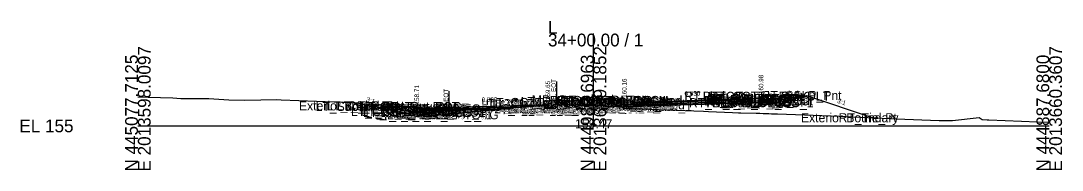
# Model space of a CAD drawing. Extents: x -26 to 4203, y -10 to 9526.
# Drawn here: x 1974.3 to 2202.8, y 3990.3 to 4023 of the extents above; entities that cross this region are included whole.
import ezdxf

# ---------------------------------------------------------------- set-up
doc = ezdxf.new("R2010")
doc.units = 0
for name, color, linetype in [('Default', 7, 'Continuous'), ('Exist CMT Pavement', 7, 'Continuous'), ('Exist Cross Section Cell', 7, 'Continuous'), ('Exist XS Center Line Elevation Label', 7, 'Continuous'), ('Exist XS Ground Line', 7, 'Continuous'), ('Prop CMT Conc Surface', 7, 'Continuous'), ('Prop CMT Concrete Structures', 7, 'Continuous'), ('Prop CMT Pvmt Course 1', 7, 'Continuous'), ('Prop CMT Pvmt Course 1 CG', 7, 'Continuous'), ('Prop CMT Pvmt Course 2', 7, 'Continuous'), ('Prop CMT Pvmt Course 2 Wedge', 7, 'Continuous'), ('Prop CMT Pvmt Course 3', 7, 'Continuous'), ('Prop CMT Pvmt Course 3 Wedge', 7, 'Continuous'), ('Prop CMT Pvmt Surface', 7, 'Continuous'), ('Prop CMT Slope Grass', 7, 'Continuous'), ('Prop CMT Subgrade Earthwork', 7, 'Continuous'), ('Prop XS Hydro Elevations', 7, 'Continuous'), ('Prop XS Label Text', 7, 'Continuous'), ('Prop XS SE Text', 7, 'Continuous'), ('Prop XS Side Slope Text', 7, 'Continuous'), ('Scratch_Level_0', 7, 'Continuous')]:
    doc.layers.add(name, color=color, linetype=linetype)

msp = doc.modelspace()

# ---------------------------------------------------------------- linework, layer by layer
at = {"layer": 'Exist CMT Pavement'}
msp.add_lwpolyline([(2067.12, 4002.45), (2067.13, 4002.45), (2067.16, 4002.46), (2068.21, 4002.58), (2068.52, 4002.61), (2069.01, 4002.66), (2071.22, 4002.88), (2072.32, 4002.99), (2073.85, 4003.16), (2076.18, 4003.37), (2076.47, 4003.39), (2076.62, 4003.4), (2077.08, 4003.45), (2079.21, 4003.65), (2079.59, 4003.68), (2080.15, 4003.74), (2081.71, 4003.88), (2084.01, 4004.11), (2084.33, 4004.14), (2084.99, 4004.19), (2086.46, 4004.32), (2086.96, 4004.36), (2087.93, 4004.44), (2089.59, 4004.57), (2091.11, 4004.67), (2091.25, 4004.68)], dxfattribs=at)
at = {"layer": 'Exist Cross Section Cell'}
for p, q in [((2100, 4000), (2100, 4020.22)), ((2000, 4000), (2100, 4000)), ((2100, 4000), (2200, 4000))]:
    msp.add_line(p, q, dxfattribs=at)
at = {"layer": 'Exist XS Ground Line'}
msp.add_lwpolyline([(2000, 4006.35), (2002.22, 4006.27), (2007.64, 4006.14), (2009.42, 4006.04), (2015.57, 4005.97), (2019.95, 4005.74), (2023.49, 4005.64), (2030.47, 4005.75), (2031.42, 4005.73), (2046.98, 4005.12), (2048.18, 4005.07), (2049.4, 4004.79), (2059.55, 4002.61), (2063.84, 4002.53), (2067.11, 4002.45), (2068.21, 4002.58), (2068.52, 4002.61), (2069.01, 4002.66), (2071.22, 4002.88), (2072.32, 4002.99), (2073.85, 4003.16), (2076.62, 4003.4), (2077.08, 4003.45), (2079.21, 4003.65), (2079.59, 4003.68), (2080.15, 4003.74), (2081.71, 4003.88), (2084.01, 4004.11), (2084.33, 4004.14), (2084.99, 4004.19), (2086.46, 4004.32), (2086.96, 4004.36), (2087.93, 4004.44), (2089.59, 4004.57), (2091.11, 4004.67), (2091.84, 4004.71), (2094.89, 4004.62), (2098.89, 4004.5), (2100, 4004.47), (2106.09, 4004.29), (2106.59, 4003.89), (2122.02, 4003.29), (2124.09, 4003.23), (2125.2, 4003.18), (2130.46, 4002.97), (2131.84, 4002.9), (2132.29, 4002.89), (2135.7, 4002.79), (2136.49, 4002.77), (2137.21, 4002.74), (2137.88, 4002.72), (2138.49, 4002.7), (2139.04, 4002.68), (2139.53, 4002.67), (2139.96, 4002.65), (2140.34, 4002.64), (2146.26, 4002.39), (2153.93, 4002.1), (2156.78, 4002), (2158.63, 4001.91), (2166.38, 4001.58), (2175.84, 4001.19), (2178.74, 4001.15), (2184.63, 4001.83), (2185.31, 4001.38), (2186.37, 4001.32), (2186.71, 4001.3), (2193.89, 4001.02), (2197.32, 4000.91), (2200, 4000.85)], dxfattribs=at)
at = {"layer": 'Prop CMT Conc Surface'}
for points in [[(2136.75, 4005.98), (2136.75, 4006.48), (2137.25, 4006.48)], [(2141.25, 4006.57), (2146.25, 4006.67)], [(2058.75, 4004.25), (2053.75, 4004.35)], [(2061.2, 4003.71), (2061.2, 4004.21), (2060.7, 4004.21)], [(2089.22, 4004.63), (2089.97, 4004.65), (2089.97, 4004.82), (2090.73, 4005.07)], [(2108.75, 4005.22), (2106.75, 4005.16), (2106.75, 4005.32), (2106, 4005.57)], [(2134.75, 4006), (2136.75, 4005.98)], [(2063.2, 4003.85), (2061.2, 4003.71)]]:
    msp.add_lwpolyline(points, dxfattribs=at)
at = {"layer": 'Prop CMT Concrete Structures'}
for points in [[(2134.75, 4006), (2136.75, 4005.98), (2136.75, 4006.48), (2137.25, 4006.48)], [(2137.25, 4006.48), (2137.25, 4005.49), (2134.75, 4005.41)], [(2146.25, 4006.67), (2141.25, 4006.57)], [(2141.25, 4006.57), (2141.25, 4006.23)], [(2141.25, 4006.23), (2146.25, 4006.33)], [(2146.25, 4006.33), (2146.25, 4006.67)], [(2053.75, 4004.02), (2053.75, 4004.35)], [(2053.75, 4004.35), (2058.75, 4004.25)], [(2058.75, 4003.92), (2053.75, 4004.02)], [(2058.75, 4004.25), (2058.75, 4003.92)], [(2063.2, 4003.85), (2061.2, 4003.71), (2061.2, 4004.21), (2060.7, 4004.21)], [(2060.7, 4004.21), (2060.7, 4003.19), (2063.2, 4003.27)], [(2089.22, 4004.63), (2089.97, 4004.65), (2089.97, 4004.82), (2090.73, 4005.07)], [(2089.22, 4004.05), (2089.22, 4004.63)], [(2090.73, 4004.09), (2089.22, 4004.05)], [(2090.73, 4005.07), (2090.73, 4004.09)], [(2108.75, 4005.22), (2106.75, 4005.16), (2106.75, 4005.32), (2106, 4005.57)], [(2106, 4005.57), (2106, 4004.55)], [(2106, 4004.55), (2108.75, 4004.63)], [(2108.75, 4004.63), (2108.75, 4005.22)], [(2134.75, 4005.41), (2134.75, 4006)], [(2063.2, 4003.27), (2063.2, 4003.85)]]:
    msp.add_lwpolyline(points, dxfattribs=at)
at = {"layer": 'Prop CMT Pvmt Course 1'}
for points in [[(2089.22, 4004.63), (2063.2, 4003.85)], [(2063.2, 4003.6), (2067.12, 4003.72), (2089.22, 4004.38)], [(2089.22, 4004.38), (2089.22, 4004.63)], [(2089.22, 4004.38), (2089.22, 4004.38)], [(2108.75, 4005.22), (2134.75, 4006)], [(2134.75, 4005.75), (2108.75, 4004.97)], [(2108.75, 4004.97), (2108.75, 4005.22)], [(2108.75, 4004.97), (2108.75, 4004.97), (2108.75, 4004.97)], [(2134.75, 4006), (2134.75, 4005.75)], [(2063.2, 4003.85), (2063.2, 4003.6)]]:
    msp.add_lwpolyline(points, dxfattribs=at)
at = {"layer": 'Prop CMT Pvmt Course 1 CG'}
for points in [[(2089.22, 4004.05), (2091.23, 4004.11), (2091.55, 4003.79)], [(2089.22, 4003.72), (2089.22, 4004.05)], [(2108.75, 4004.63), (2105.5, 4004.54), (2105.16, 4004.19)], [(2105.16, 4004.19), (2108.75, 4004.3)], [(2108.75, 4004.3), (2108.75, 4004.63)], [(2134.75, 4005.41), (2137.75, 4005.5), (2138.07, 4005.18)], [(2134.75, 4005.08), (2134.75, 4005.41)], [(2138.07, 4005.18), (2134.75, 4005.08)], [(2063.2, 4003.27), (2060.2, 4003.18), (2059.86, 4002.83)], [(2059.86, 4002.83), (2063.2, 4002.93)], [(2063.2, 4002.93), (2063.2, 4003.27)], [(2091.55, 4003.79), (2089.22, 4003.72)]]:
    msp.add_lwpolyline(points, dxfattribs=at)
at = {"layer": 'Prop CMT Pvmt Course 2'}
msp.add_lwpolyline([(2089.22, 4004.38), (2089.22, 4004.05), (2089.22, 4004.05)], close=True, dxfattribs=at)
for points in [[(2089.22, 4004.38), (2089.22, 4004.38)], [(2108.75, 4004.97), (2134.75, 4005.75)], [(2134.75, 4005.41), (2108.75, 4004.63)], [(2108.75, 4004.63), (2108.75, 4004.97)], [(2134.75, 4005.75), (2134.75, 4005.41)], [(2067.12, 4003.72), (2063.2, 4003.6)], [(2063.2, 4003.6), (2063.2, 4003.27)], [(2063.2, 4003.27), (2067.12, 4003.39)], [(2067.12, 4003.39), (2067.12, 4003.72)]]:
    msp.add_lwpolyline(points, dxfattribs=at)
at = {"layer": 'Prop CMT Pvmt Course 2 Wedge'}
for points in [[(2067.12, 4003.72), (2067.13, 4003.72), (2067.16, 4003.72), (2068.21, 4003.75), (2068.52, 4003.76), (2069.01, 4003.77), (2071.22, 4003.84), (2072.32, 4003.87), (2073.85, 4003.92), (2076.18, 4003.99), (2076.47, 4004), (2076.62, 4004), (2077.08, 4004.02), (2079.21, 4004.08), (2079.59, 4004.09), (2080.15, 4004.11), (2081.71, 4004.16), (2084.01, 4004.22), (2084.33, 4004.23), (2084.99, 4004.25), (2086.03, 4004.29)], [(2086.03, 4004.29), (2084.99, 4004.19), (2084.33, 4004.14), (2084.01, 4004.11), (2081.71, 4003.88), (2080.77, 4003.79), (2080.15, 4003.78), (2079.59, 4003.76), (2079.21, 4003.75), (2077.08, 4003.68), (2076.62, 4003.67), (2076.47, 4003.67), (2076.18, 4003.66), (2073.85, 4003.59), (2072.32, 4003.54), (2071.22, 4003.51), (2069.01, 4003.44), (2068.52, 4003.43), (2068.21, 4003.42), (2067.16, 4003.39), (2067.13, 4003.39), (2067.12, 4003.38)], [(2067.12, 4003.38), (2067.12, 4003.72)]]:
    msp.add_lwpolyline(points, dxfattribs=at)
at = {"layer": 'Prop CMT Pvmt Course 3'}
for points in [[(2089.22, 4004.05), (2089.22, 4004.05), (2089.22, 4003.72), (2089.22, 4003.72)], [(2089.22, 4003.72), (2089.22, 4004.05)], [(2108.75, 4004.63), (2134.75, 4005.41)], [(2134.75, 4005.08), (2108.75, 4004.3)], [(2108.75, 4004.3), (2108.75, 4004.63)], [(2134.75, 4005.41), (2134.75, 4005.08)], [(2067.12, 4003.39), (2063.2, 4003.27)], [(2063.2, 4003.27), (2063.2, 4002.93)], [(2063.2, 4002.93), (2067.12, 4003.05)], [(2067.12, 4003.05), (2067.12, 4003.39)]]:
    msp.add_lwpolyline(points, dxfattribs=at)
at = {"layer": 'Prop CMT Pvmt Course 3 Wedge'}
for points in [[(2067.12, 4003.39), (2067.13, 4003.39), (2067.16, 4003.39), (2068.21, 4003.42), (2068.52, 4003.43), (2069.01, 4003.44), (2071.22, 4003.51), (2072.32, 4003.54), (2073.85, 4003.59), (2076.18, 4003.66), (2076.47, 4003.67), (2076.62, 4003.67), (2077.08, 4003.68), (2079.21, 4003.75), (2079.59, 4003.76), (2080.15, 4003.78), (2080.78, 4003.79)], [(2080.78, 4003.79), (2080.15, 4003.74), (2079.59, 4003.68), (2079.21, 4003.65), (2077.08, 4003.45), (2076.62, 4003.4), (2076.47, 4003.39), (2076.18, 4003.37), (2073.85, 4003.16), (2072.32, 4002.99), (2071.22, 4002.88), (2069.01, 4002.66), (2068.52, 4002.61), (2068.21, 4002.58), (2067.16, 4002.46), (2067.13, 4002.45), (2067.12, 4002.45)], [(2067.12, 4002.45), (2067.12, 4003.39)]]:
    msp.add_lwpolyline(points, dxfattribs=at)
at = {"layer": 'Prop CMT Pvmt Surface'}
for points in [[(2089.22, 4004.63), (2063.2, 4003.85)], [(2108.75, 4005.22), (2134.75, 4006)]]:
    msp.add_lwpolyline(points, dxfattribs=at)
at = {"layer": 'Prop CMT Slope Grass'}
for points in [[(2137.25, 4006.48), (2146.75, 4006.67)], [(2146.75, 4006.67), (2161.37, 4001.79)], [(2051.2, 4004.4), (2051.19, 4004.4)], [(2060.7, 4004.21), (2051.2, 4004.4)], [(2090.73, 4005.07), (2098.3, 4005.73)], [(2106, 4005.57), (2098.3, 4005.73)]]:
    msp.add_lwpolyline(points, dxfattribs=at)
at = {"layer": 'Prop CMT Subgrade Earthwork'}
for points in [[(2134.75, 4005.08), (2138.07, 4005.18), (2139.41, 4006.52)], [(2063.2, 4002.93), (2059.86, 4002.83), (2058.44, 4004.26)], [(2089.22, 4003.72), (2089.22, 4004.62)], [(2093.04, 4005.27), (2091.55, 4003.79)], [(2103.73, 4005.62), (2105.16, 4004.19)], [(2105.16, 4004.19), (2108.75, 4004.3)], [(2108.75, 4004.3), (2134.75, 4005.08)], [(2108.75, 4004.3), (2108.75, 4004.3)], [(2108.75, 4004.3), (2108.75, 4004.3)], [(2134.75, 4005.08), (2134.75, 4005.08)], [(2067.12, 4003.05), (2063.2, 4002.93)], [(2063.2, 4002.93), (2063.2, 4002.93)], [(2067.12, 4003.05), (2067.12, 4002.45)], [(2091.55, 4003.79), (2089.22, 4003.72)], [(2089.22, 4003.72), (2089.22, 4003.72)], [(2089.22, 4003.72), (2089.22, 4003.72)]]:
    msp.add_lwpolyline(points, dxfattribs=at)
at = {"layer": 'Prop XS Label Text'}
for p, q in [((2091.84, 4009.71), (2091.84, 4004.71)), ((2068.21, 4007.58), (2068.21, 4002.58))]:
    msp.add_line(p, q, dxfattribs=at)

# ---------------------------------------------------------------- texts
at = {"layer": 'Default'}
msp.add_text('-', height=0.0001, dxfattribs=at).set_placement((2000, 4000))
at = {"layer": 'Exist Cross Section Cell'}
for s, p in [('L', (2090, 4020.22)), ('34+00.00 / 1', (2090, 4017.42)), ('EL 155', (1974, 3998.6))]:
    msp.add_text(s, height=2.8, dxfattribs=at).set_placement(p)
for s, p in [('N 445077.7125', (2000, 3990)), ('E 2013598.0097', (2002.8, 3990)), ('N 444982.6963', (2100, 3990)), ('E 2013629.1852', (2102.8, 3990)), ('N 444887.6800', (2200, 3990)), ('E 2013660.3607', (2202.8, 3990))]:
    msp.add_text(s, height=2.8, rotation=90, dxfattribs=at).set_placement(p)
at = {"layer": 'Exist XS Center Line Elevation Label'}
msp.add_text('159.47', height=2, dxfattribs=at).set_placement((2095.94, 3999.47))
at = {"layer": 'Prop XS Hydro Elevations'}
for s, p in [('160.98', (2137.25, 4006.98)), ('158.71', (2061.7, 4004.71)), ('159.65', (2090.47, 4005.65)), ('160.16', (2107.25, 4006.16))]:
    msp.add_text(s, height=1, rotation=90, dxfattribs=at).set_placement(p)
at = {"layer": 'Prop XS Label Text'}
for p in [(2091.74, 4005.74), (2068.11, 4003.6)]:
    msp.add_text('E. EOT', height=1, rotation=90, dxfattribs=at).set_placement(p)
at = {"layer": 'Prop XS SE Text'}
for rotation, p in [(1.7175, (2075.45, 4005.22)), (1.7184, (2119.97, 4006.55))]:
    msp.add_text('0.030', height=1, rotation=rotation, dxfattribs=at).set_placement(p)
at = {"layer": 'Prop XS Side Slope Text'}
for p in [(2050.04, 4005.42), (2153.39, 4005.08)]:
    msp.add_text('3:1', height=1, rotation=341.5651, dxfattribs=at).set_placement(p)
at = {"layer": 'Scratch_Level_0'}
for s, p in [('LT_CG_Top_BOC_Med', (2077.15, 4004.13)), ('LT_Sub_DLT_In', (2084.01, 4004.33)), ('MD_Crown Point', (2086.45, 4004.71)), ('RT_CG_Top_BOC_Med', (2090.35, 4004.57)), ('RT_CG_Top_BOC In', (2091.97, 4004.57)), ('RT_CG_Top FOC In', (2092.61, 4004.32)), ('RT_Sub_DLT_In', (2092.63, 4004.62)), ('RT_CG_Top_Gut In', (2092.64, 4004.16)), ('RT_PV1_PGL', (2100.48, 4004.22)), ('RT_Sub_Trench_Out_DLT', (2119.93, 4005.52)), ('RT_Sub_OEOT_CG_1', (2120.92, 4004.08)), ('RT_CG_Top_Face', (2123.96, 4005.48)), ('RT_CG1_Shelf_Out', (2124.25, 4004.5)), ('RT_CG_Bot_IE', (2124.62, 4004.41)), ('RT_Sub_OEOT', (2124.78, 4004.08)), ('RT_PV2_OEOT', (2124.88, 4004.75)), ('RT_PV3_OEOT', (2124.88, 4004.41)), ('RT_CG_Top_Gut', (2124.94, 4004.98)), ('RT_PV1_OEOT', (2125.44, 4005)), ('RT_CG_Top_BOC', (2125.49, 4005.48)), ('RT_CG_Bot_BOC', (2125.52, 4004.49)), ('RT_Sub_OEOP', (2128.14, 4004.18)), ('RT_CSLP_Pnt', (2136.88, 4005.67)), ('Exterior Boundary', (2035.34, 4003.4)), ('LT_Sub_Trench_Out_DLT', (2039, 4003.26)), ('LT_CSLP_Pnt', (2041.37, 4003.4)), ('LT_Tie_Pt', (2043.64, 4003.4)), ('LT_CG1_Shelf_Out', (2046.75, 4002.18)), ('LT_CG_Top_Face', (2048.46, 4003.21)), ('LT_CG_Top_BOC', (2048.98, 4003.21)), ('LT_CG_Bot_BOC', (2049.02, 4002.19)), ('LT_Sub_OEOT_CG_1', (2049.42, 4001.93)), ('LT_CG_Top_Gut', (2049.44, 4002.71)), ('LT_Sub_OEOP', (2049.97, 4001.83)), ('LT_CG_Bot_IE', (2053.12, 4002.27)), ('LT_Sub_OEOT', (2053.28, 4001.93)), ('LT_PV2_OEOT', (2053.38, 4002.6)), ('LT_PV3_OEOT', (2053.38, 4002.27)), ('LT_PV1_OEOT', (2053.94, 4002.85)), ('LT_Sub_OEEOP', (2056.33, 4002.05)), ('LT_PV2_OEEOP', (2056.42, 4002.72)), ('LT_PV3_OEEOP', (2056.42, 4002.39)), ('LT_CG_Top_Face_Med', (2075.37, 4003.88)), ('LT_CG_Top_Gut_Med', (2076.35, 4003.72)), ('LT_CG_Bot_BOC_Med', (2077.19, 4003.15)), ('LT_CG_Bot_IE_Med', (2077.31, 4003.11)), ('LT_PV_Sub_Tie_In', (2077.82, 4003.68)), ('LT_Sub_IEOT_CG_1', (2078.12, 4002.78)), ('LT_PV_IEEOP_EG', (2079.44, 4003.68)), ('LT_Sub_IEEOP', (2081.11, 4002.78)), ('LT_PV2_IEEOP', (2081.2, 4003.44)), ('LT_PV3_IEEOP', (2081.2, 4003.11)), ('LT_CG1_Shelf_In', (2081.43, 4003.17)), ('LT_Sub_PGL', (2082.37, 4002.78)), ('LT_PV2_PGL', (2082.46, 4003.44)), ('LT_PV3_PGL', (2082.46, 4003.11)), ('LT_PV1_PGL', (2083.03, 4003.69)), ('LT_Sub_IEOP', (2084.34, 4002.85)), ('RT_CG_Bot BOC In', (2091.84, 4003.55)), ('RT_CG1_Shelf_In', (2093.63, 4003.54)), ('RT_CG_Bot_IE_Med', (2094.77, 4003.63)), ('RT_Sub_IEOT_CG_1', (2095.57, 4003.3)), ('RT_Sub_IEOP', (2095.86, 4003.19)), ('RT_Sub_OEEOP', (2097.92, 4003.3)), ('RT_PV2_OEEOP', (2098.01, 4003.97)), ('RT_PV3_OEEOP', (2098.01, 4003.63)), ('RT_Sub_IEEOP', (2098.56, 4003.3)), ('RT_PV2_IEEOP', (2098.66, 4003.97)), ('RT_Sub_PGL', (2099.82, 4003.3)), ('RT_PV2_PGL', (2099.92, 4003.97)), ('LT_PV_Sub_Tie_Out', (2052.06, 4001.45)), ('LT_PV_OEEOP_EG', (2054.66, 4001.45)), ('Exterior Boundary', (2145.51, 4000.79)), ('RT_Tie_Pt', (2153.77, 4000.79))]:
    msp.add_text(s, height=2, dxfattribs=at).set_placement(p)

doc.saveas('drawing.dxf')
